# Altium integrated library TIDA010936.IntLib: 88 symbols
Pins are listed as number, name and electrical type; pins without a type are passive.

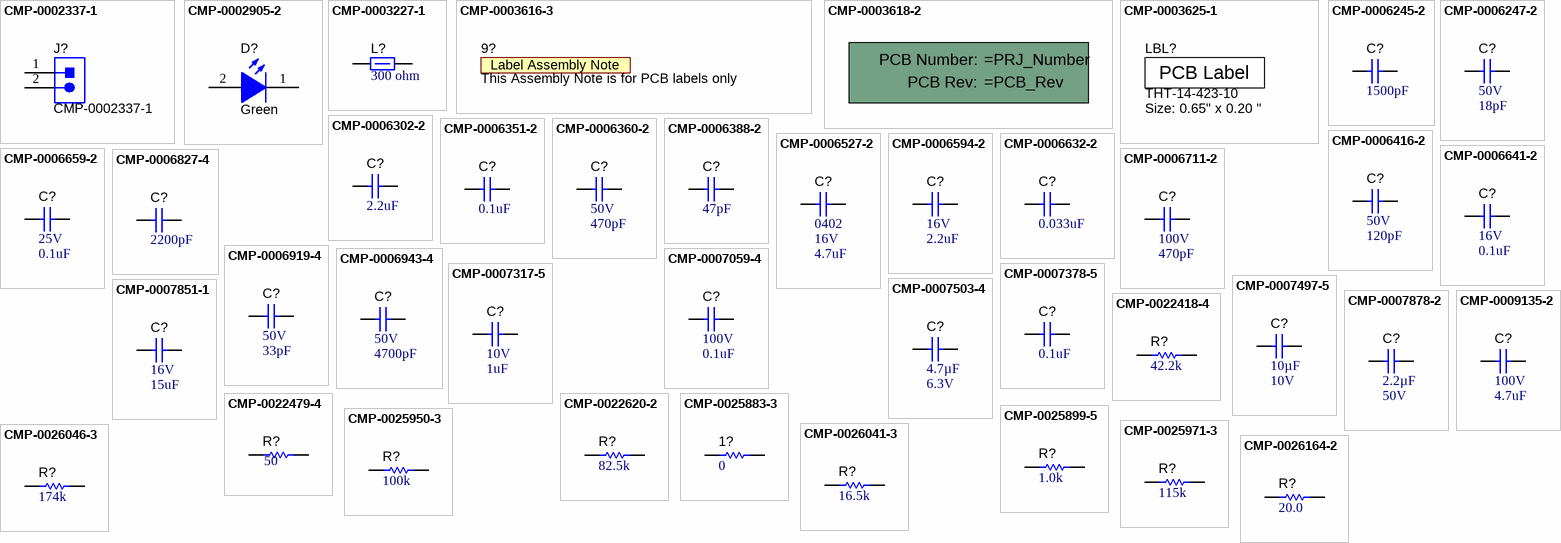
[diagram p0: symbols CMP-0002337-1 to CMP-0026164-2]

## CMP-0002337-1
designator J?
Header, 100mil, 2x1, Tin, TH; PartNumber: PEC02SAAN; Manufacturer: Sullins Connector Solutions; Pitch_mm: 2.54; Gender: Male; Shrouded: N; Row_Count: 1; Current_A: 3A; Voltage_V: 1.8kV; Cert_UL: Y; CNHeader: TRUE; Green_Lifecycle: Not Set; Green_REACh: Incomplete; CT: FALSE
footprint CONN_PEC02SAAN (SULLINS)
pins: 1, 2
1 alternate drawing of the same symbol

## CMP-0002905-2
designator D?  value Green  (hidden comment: CMP-0002905-2)
LED, Green, SMD; Manufacturer: Wurth Elektronik; PartNumber: 150060GS75000; Manufacturer: Wurth Electronics; Type: InGaN; Vf_V: 3.2V; Io_A: 20mA; Tjmax_C: 85°C; Value1: W; Angle: 140
footprint WL-SMCW_GREEN (WURTH)
pins: 1 K, 2 A

## CMP-0003227-1
designator L?  value 300 ohm  (hidden comment: CMP-0003227-1)
Ferrite Bead, 300 ohm @ 100 MHz, 0.2 A, 0402; PartNumber: 74279272; Manufacturer: Wurth Elektronik; Imax_A: 200mA; DCR_ohm: 0.8; Value1: 0.8 ohm; Value2: 0.2A; ZTyp@100MHz_Ohm: 300; Ztyp@1GHz_Ohm: 316.308; SizeAreaWB_mm2: 3; SizeZ_mm: 0.6; SizeX_mm: 1; SizeY_mm: 0.5
footprint 0402 (0402 from SM-752 data)
footprint 0402S (Based on C0402S footprint from PADS legacy)
footprint 0402L (0402 from SM-752 data)
footprint 0402M (0402 from SM-752 data)
pins: 1, 2

## CMP-0003616-3
designator 9?, comment This Assembly Note is for PCB labels only  (no BOM)
Key: AssemblyNoteLabel
footprint AssemblyNoteLabel (Assembly Note for PCB Labels)

## CMP-0003618-2
designator !PCB?, comment Printed Circuit Board  (value not drawn)  (mechanical)
Manufacturer: Any; CompType: PCB
1 alternate drawing of the same symbol

## CMP-0003625-1
designator LBL?, comment THT-14-423-10  Note: Size: 0.65" x 0.20 "
Thermal Transfer Printable Labels, 0.650" W x 0.200" H - 10,000 per roll; Manufacturer: Brady; CompType: Label
footprint Label_650x200 (Thermal Transfer Label)

## CMP-0006245-2
designator C?  ValueDisplayed: 1500pF  (hidden comment: CMP-0006245-2)
CAP, CERM, 1500 pF, 25 V, +/- 5%, C0G/NP0, 0402; PartNumber: C0402H152J3GAC7867; Manufacturer: Kemet; Polarized: N; CompType: Capacitor; Value: 1500pF; U/M: EA; Cap_F: 1.5nF; Value1: Unknown; VDC_V: 25V; TaMin_C: -55°C; TaMax_C: 200°C; Cap_Case: 0402; AEC Category: Q200; SizeArea_mm2: 0.5; SizeAreaWB_mm2: 3; SizeX_mm: 1; SizeZ_mm: 0.6
footprint 0402 (0402 from SM-752 data)
footprint 0402S (Based on C0402S footprint from PADS legacy)
footprint 0402L (0402 from SM-752 data)
footprint 0402M (0402 from SM-752 data)
pins: 1, 2

## CMP-0006247-2
designator C?, comment VDC_V: 50V  ValueDisplayed: 18pF  (hidden comment: C1005C0G1H180J050BA)
CAP, CERM, 18 pF, 50 V, +/- 5%, C0G/NP0, 0402; Manufacturer: TDK; TaMin_C: -55°C; Polarized: N; SizeAreaWB_mm2: 3; Value1: Unknown; U/M: EA; Value: 18pF; TaMax_C: 125°C; SizeZ_mm: 0.6; SizeX_mm: 1; SizeY_mm: 0.5; Cap_Case: 0402; CompType: Capacitor; AEC Category: Q200
footprint 0402 (0402 from SM-752 data)
footprint 0402S (Based on C0402S footprint from PADS legacy)
footprint 0402L (0402 from SM-752 data)
footprint 0402M (0402 from SM-752 data)
pins: 1, 2

## CMP-0006302-2
designator C?, comment ValueDisplayed: 2.2uF  (hidden comment: C1005X7S1A225K050BC)
CAP, CERM, 2.2 uF, 10 V, +/- 10%, X7S, 0402; Manufacturer: TDK; Polarized: N; CompType: Capacitor; Value: 2.2uF; U/M: EA; Cap_F: 2.2µF; ESR_ohm: 5.925m; Value1: 0.005925 ohm; VDC_V: 10V; IRMS_A: 2.0559A; TaMin_C: -55°C; TaMax_C: 125°C; Cap_Case: 0402_065; SizeArea_mm2: 0.5; SizeAreaWB_mm2: 3; SizeX_mm: 1; SizeZ_mm: 0.65; AEC Category: Q200
footprint 0402_065 (0402)
footprint 0402_065S (Based on C0402S footprint from PADS legacy)
footprint 0402_065L (0402)
footprint 0402_065M (0402)
pins: 1, 2

## CMP-0006351-2
designator C?  ValueDisplayed: 0.1uF  (hidden comment: CMP-0006351-2)
CAP, CERM, 0.1 uF, 16 V, +/- 10%, X7R, 0402; PartNumber: GCM155R71C104KA55D; Manufacturer: MuRata; Polarized: N; CompType: Capacitor; Value: 0.1uF; U/M: EA; Cap_F: 100nF; Value1: Unknown; VDC_V: 16V; TaMin_C: -55°C; TaMax_C: 125°C; Cap_Case: 0402; AEC Category: Q200; SizeAreaWB_mm2: 3; SizeZ_mm: 0.6; SizeX_mm: 1; SizeY_mm: 0.5
footprint 0402 (0402 from SM-752 data)
footprint 0402S (Based on C0402S footprint from PADS legacy)
footprint 0402L (0402 from SM-752 data)
footprint 0402M (0402 from SM-752 data)
pins: 1, 2

## CMP-0006360-2
designator C?, comment VDC_V: 50V  ValueDisplayed: 470pF  (hidden comment: GCM155R71H471KA37D)
CAP, CERM, 470 pF, 50 V, +/- 10%, X7R, AEC-Q200 Grade 1, 0402; Manufacturer: MuRata; TaMin_C: -55°C; Polarized: N; SizeAreaWB_mm2: 3; Value1: Unknown; U/M: EA; Value: 470pF; TaMax_C: 125°C; SizeZ_mm: 0.6; SizeX_mm: 1; SizeY_mm: 0.5; Cap_Case: 0402; CompType: Capacitor; AEC Qualified: Y; AEC Category: Q200
footprint 0402 (0402 from SM-752 data)
footprint 0402S (Based on C0402S footprint from PADS legacy)
footprint 0402L (0402 from SM-752 data)
footprint 0402M (0402 from SM-752 data)
pins: 1, 2

## CMP-0006388-2
designator C?  ValueDisplayed: 47pF  (hidden comment: CMP-0006388-2)
CAP, CERM, 47 pF, 25 V, +/- 5%, C0G/NP0, 0402; PartNumber: GRM1555C1E470JA01D; Manufacturer: MuRata; Polarized: N; CompType: Capacitor; Value: 47pF; U/M: EA; Value1: Unknown; VDC_V: 25V; TaMin_C: -55°C; TaMax_C: 125°C; Cap_Case: 0402; AEC Category: Q200; SizeAreaWB_mm2: 3; SizeZ_mm: 0.6; SizeX_mm: 1; SizeY_mm: 0.5
footprint 0402 (0402 from SM-752 data)
footprint 0402S (Based on C0402S footprint from PADS legacy)
footprint 0402L (0402 from SM-752 data)
footprint 0402M (0402 from SM-752 data)
pins: 1, 2

## CMP-0006416-2
designator C?, comment VDC_V: 50V  ValueDisplayed: 120pF  (hidden comment: GRM1555C1H121FA01D)
CAP, CERM, 120 pF, 50 V, +/- 1%, C0G/NP0, 0402; Manufacturer: MuRata; TaMin_C: -55°C; Polarized: N; SizeAreaWB_mm2: 3; Value1: Unknown; U/M: EA; Value: 120pF; TaMax_C: 125°C; SizeZ_mm: 0.6; SizeX_mm: 1; SizeY_mm: 0.5; Cap_Case: 0402; CompType: Capacitor; AEC Category: Q200
footprint 0402 (0402 from SM-752 data)
footprint 0402S (Based on C0402S footprint from PADS legacy)
footprint 0402L (0402 from SM-752 data)
footprint 0402M (0402 from SM-752 data)
pins: 1, 2

## CMP-0006527-2
designator C?, comment PackageReference: 0402  VDC_V: 16V  ValueDisplayed: 4.7uF  (hidden comment: GRM155D81C475ME15D)
CAP, CERM, 4.7 uF, 16 V, +/- 20%, X6T, 0402; Manufacturer: MuRata; TaMin_C: -55°C; Polarized: N; SizeAreaWB_mm2: 3; Value1: Unknown; U/M: EA; Value: 4.7uF; TaMax_C: 105°C; SizeZ_mm: 0.7; SizeX_mm: 1; SizeY_mm: 0.5; CompType: Capacitor; Cap_F: 4.7µF; AEC Category: Q200
footprint 0402_070 (SMD, 2-Leads, Body 1.2x0.7mm, Height 0.7mm)
pins: 1, 2

## CMP-0006594-2
designator C?, comment VDC_V: 16V  ValueDisplayed: 2.2uF  (hidden comment: GRM155R61C225KE11D)
CAP, CERM, 2.2 uF, 16 V, +/- 10%, X5R, 0402; Manufacturer: MuRata; TaMin_C: -55°C; Polarized: N; SizeAreaWB_mm2: 3; Value1: Unknown; U/M: EA; Value: 2.2uF; TaMax_C: 85°C; SizeZ_mm: 0.6; SizeX_mm: 1; SizeY_mm: 0.5; Cap_Case: 0402; CompType: Capacitor; Cap_F: 2.2µF; AEC Category: Q200
footprint 0402 (0402 from SM-752 data)
footprint 0402S (Based on C0402S footprint from PADS legacy)
footprint 0402L (0402 from SM-752 data)
footprint 0402M (0402 from SM-752 data)
pins: 1, 2

## CMP-0006632-2
designator C?  ValueDisplayed: 0.033uF  (hidden comment: CMP-0006632-2)
CAP, CERM, 0.033 uF, 10 V, +/- 10%, X7R, 0402; PartNumber: GRM155R71A333KA01D; Manufacturer: MuRata; Polarized: N; CompType: Capacitor; U/M: EA; Cap_F: 33nF; Value1: Unknown; VDC_V: 10V; TaMin_C: -55°C; TaMax_C: 125°C; Cap_Case: 0402; AEC Category: Q200; SizeArea_mm2: 0.5; SizeAreaWB_mm2: 3; SizeX_mm: 1; SizeZ_mm: 0.6
footprint 0402 (0402 from SM-752 data)
footprint 0402S (Based on C0402S footprint from PADS legacy)
footprint 0402L (0402 from SM-752 data)
footprint 0402M (0402 from SM-752 data)
pins: 1, 2

## CMP-0006641-2
designator C?, comment VDC_V: 16V  ValueDisplayed: 0.1uF  (hidden comment: GRM155R71C104KA88D)
CAP, CERM, 0.1 uF, 16 V, +/- 10%, X7R, 0402; Manufacturer: MuRata; Manufacturer Part Number: GRM155-R7-1C-104K-A88-D; TaMin_C: -55°C; Polarized: N; SizeAreaWB_mm2: 3; Value1: Unknown; U/M: EA; Value: 0.1uF; TaMax_C: 125°C; SizeZ_mm: 0.6; SizeX_mm: 1; SizeY_mm: 0.5; Cap_Case: 0402; CompType: Capacitor; Cap_F: 100nF; AEC Category: Q200
footprint 0402 (0402 from SM-752 data)
footprint 0402S (Based on C0402S footprint from PADS legacy)
footprint 0402L (0402 from SM-752 data)
footprint 0402M (0402 from SM-752 data)
pins: 1, 2

## CMP-0006659-2
designator C?, comment VDC_V: 25V  ValueDisplayed: 0.1uF  (hidden comment: GRM155R71E104KE14D)
CAP, CERM, 0.1 uF, 25 V, +/- 10%, X7R, 0402; Manufacturer: MuRata; TaMin_C: -55°C; Polarized: N; SizeAreaWB_mm2: 3; Value1: Unknown; U/M: EA; Value: 0.1uF; TaMax_C: 125°C; SizeZ_mm: 0.6; SizeX_mm: 1; SizeY_mm: 0.5; Cap_Case: 0402; CompType: Capacitor; Cap_F: 100nF; AEC Category: Q200
footprint 0402 (0402 from SM-752 data)
footprint 0402S (Based on C0402S footprint from PADS legacy)
footprint 0402L (0402 from SM-752 data)
footprint 0402M (0402 from SM-752 data)
pins: 1, 2

## CMP-0006711-2
designator C?, comment VDC_V: 100V  ValueDisplayed: 470pF  (hidden comment: GRM155R72A471KA01D)
CAP, CERM, 470 pF, 100 V, +/- 10%, X7R, 0402; Manufacturer: MuRata; TaMin_C: -55°C; Polarized: N; SizeAreaWB_mm2: 3; Value1: Unknown; U/M: EA; Value: 470pF; TaMax_C: 125°C; SizeZ_mm: 0.6; SizeX_mm: 1; SizeY_mm: 0.5; Cap_Case: 0402; CompType: Capacitor; AEC Category: Q200
footprint 0402 (0402 from SM-752 data)
footprint 0402S (Based on C0402S footprint from PADS legacy)
footprint 0402L (0402 from SM-752 data)
footprint 0402M (0402 from SM-752 data)
pins: 1, 2

## CMP-0006827-4
designator C?  ValueDisplayed: 2200pF  (hidden comment: CMP-0006827-4)
CAP, CERM, 2200 pF, 16 V, +/- 10%, X7R, 0603; PartNumber: 885012206036; Manufacturer: Wurth Elektronik; Polarized: N; CompType: Capacitor; Value: 2200pF; U/M: EA; Cap_F: 2.2nF; Value1: Unknown; VDC_V: 16V; TaMin_C: -55°C; TaMax_C: 125°C; Cap_Case: 0603; AEC Category: Q200; SizeArea_mm2: 1.28; SizeAreaWB_mm2: 4.68; SizeX_mm: 1.6; SizeY_mm: 0.8; SizeZ_mm: 1
footprint 0603 (0603 from SM-752 data)
footprint 0603_HV (Ernesto recommended land pattern.  26 mil between pads.)
footprint 0603L (0603 from SM-752 data)
footprint 0603S
footprint 0603M (0603 from SM-752 data)
pins: 1, 2

## CMP-0006919-4
designator C?, comment VDC_V: 50V  ValueDisplayed: 33pF  (hidden comment: C0603C330J5GACTU)
CAP, CERM, 33 pF, 50 V, +/- 5%, C0G/NP0, 0603; Manufacturer: Kemet; Manufacturer Part Number: C0603C180J5GAC-TU; TaMin_C: -55°C; Polarized: N; SizeAreaWB_mm2: 4.68; Value1: Unknown; U/M: EA; Value: 33pF; TaMax_C: 125°C; SizeZ_mm: 1; SizeX_mm: 1.6; SizeY_mm: 0.8; Cap_Case: 0603; SizeArea_mm2: 1.28; CompType: Capacitor; AEC Category: Q200
footprint 0603 (0603 from SM-752 data)
footprint 0603_HV (Ernesto recommended land pattern.  26 mil between pads.)
footprint 0603L (0603 from SM-752 data)
footprint 0603S
footprint 0603M (0603 from SM-752 data)
pins: 1, 2

## CMP-0006943-4
designator C?, comment VDC_V: 50V  ValueDisplayed: 4700pF  (hidden comment: C0603C472K5RACTU)
CAP, CERM, 4700 pF, 50 V, +/- 10%, X7R, 0603; Manufacturer: Kemet; TaMin_C: -55°C; Polarized: N; SizeAreaWB_mm2: 4.68; Value1: Unknown; U/M: EA; Value: 4700pF; TaMax_C: 125°C; SizeZ_mm: 1; SizeX_mm: 1.6; SizeY_mm: 0.8; Cap_Case: 0603; SizeArea_mm2: 1.28; CompType: Capacitor; Cap_F: 4.7nF; AEC Category: Q200
footprint 0603 (0603 from SM-752 data)
footprint 0603_HV (Ernesto recommended land pattern.  26 mil between pads.)
footprint 0603L (0603 from SM-752 data)
footprint 0603S
footprint 0603M (0603 from SM-752 data)
pins: 1, 2

## CMP-0007059-4
designator C?, comment VDC_V: 100V  ValueDisplayed: 0.1uF  (hidden comment: C1608X7S2A104K080AB)
CAP, CERM, 0.1 uF, 100 V, +/- 10%, X7S, 0603; Manufacturer: TDK; TaMin_C: -55°C; ESR_ohm: 49.59m; Polarized: N; SizeAreaWB_mm2: 4.68; Value1: 0.04959 ohm; U/M: EA; Value: 0.1uF; TaMax_C: 125°C; SizeZ_mm: 1; SizeX_mm: 1.6; SizeY_mm: 0.8; Cap_Case: 0603; SizeArea_mm2: 1.28; CompType: Capacitor; Cap_F: 100nF; IRMS_A: 751.618mA; AEC Category: Q200
footprint 0603 (0603 from SM-752 data)
footprint 0603_HV (Ernesto recommended land pattern.  26 mil between pads.)
footprint 0603L (0603 from SM-752 data)
footprint 0603S
footprint 0603M (0603 from SM-752 data)
pins: 1, 2

## CMP-0007317-5
designator C?, comment VDC_V: 10V  ValueDisplayed: 1uF  (hidden comment: GRM188R61A105KA61D)
CAP, CERM, 1 uF, 10 V, +/- 10%, X5R, 0603; Manufacturer: MuRata; TaMin_C: -55°C; Polarized: N; SizeAreaWB_mm2: 4.68; Value1: Unknown; U/M: EA; Value: 1uF; TaMax_C: 85°C; SizeZ_mm: 1; SizeX_mm: 1.6; SizeY_mm: 0.8; Cap_Case: 0603; SizeArea_mm2: 1.28; CompType: Capacitor; Cap_F: 1µF; AEC Category: Q200
footprint 0603 (0603 from SM-752 data)
footprint 0603_HV (Ernesto recommended land pattern.  26 mil between pads.)
footprint 0603L (0603 from SM-752 data)
footprint 0603S
footprint 0603M (0603 from SM-752 data)
pins: 1, 2

## CMP-0007378-5
designator C?  ValueDisplayed: 0.1uF  (hidden comment: CMP-0007378-5)
CAP, CERM, 0.1 uF, 16 V, +/- 10%, X7R, 0603; PartNumber: GRM188R71C104KA01D; Manufacturer: MuRata; Polarized: N; CompType: Capacitor; Value: 0.1uF; U/M: EA; Cap_F: 100nF; Value1: Unknown; VDC_V: 16V; TaMin_C: -55°C; TaMax_C: 125°C; Cap_Case: 0603; SizeAreaWB_mm2: 4.68; SizeZ_mm: 1; SizeX_mm: 1.6; SizeY_mm: 0.8; SizeArea_mm2: 1.28; AEC Category: Q200
footprint 0603 (0603 from SM-752 data)
footprint 0603_HV (Ernesto recommended land pattern.  26 mil between pads.)
footprint 0603L (0603 from SM-752 data)
footprint 0603S
footprint 0603M (0603 from SM-752 data)
pins: 1, 2

## CMP-0007497-5
designator C?, comment Cap_F: 10µF  VDC_V: 10V  (hidden comment: GRM188Z71A106MA73D)
CAP, CERM, 10 uF, 10 V, +/- 20%, X7R, 0603; Manufacturer: MuRata; TaMin_C: -55°C; Polarized: N; SizeAreaWB_mm2: 4.68; Value1: Unknown; U/M: EA; Value: 10uF; TaMax_C: 125°C; SizeZ_mm: 1; SizeX_mm: 1.6; SizeY_mm: 0.8; Cap_Case: 0603; SizeArea_mm2: 1.28; CompType: Capacitor; AEC Category: Q200
footprint 0603 (0603 from SM-752 data)
footprint 0603_HV (Ernesto recommended land pattern.  26 mil between pads.)
footprint 0603L (0603 from SM-752 data)
footprint 0603S
footprint 0603M (0603 from SM-752 data)
pins: 1, 2

## CMP-0007503-4
designator C?, comment Cap_F: 4.7µF  VDC_V: 6.3V  (hidden comment: JMK107BB7475MA-T)
CAP, CERM, 4.7 uF, 6.3 V, +/- 10%, X7R, 0603; Manufacturer: Taiyo Yuden; TaMin_C: -55°C; Polarized: N; SizeAreaWB_mm2: 4.68; Value1: Unknown; U/M: EA; Value: 4.7uF; TaMax_C: 125°C; SizeZ_mm: 1; SizeX_mm: 1.6; SizeY_mm: 0.8; Cap_Case: 0603; SizeArea_mm2: 1.28; CompType: Capacitor; AEC Category: Q200
footprint 0603 (0603 from SM-752 data)
footprint 0603_HV (Ernesto recommended land pattern.  26 mil between pads.)
footprint 0603L (0603 from SM-752 data)
footprint 0603S
footprint 0603M (0603 from SM-752 data)
pins: 1, 2

## CMP-0007851-1
designator C?, comment VDC_V: 16V  ValueDisplayed: 15uF  (hidden comment: C2012X6S1C156M125AC)
CAP, CERM, 15 uF, 16 V, +/- 20%, X6S, 0805; Manufacturer: TDK; TaMin_C: -55°C; ESR_ohm: 1.669m; Polarized: N; SizeAreaWB_mm2: 6.75; Value1: 0.001669 ohm; U/M: EA; Value: 15uF; TaMax_C: 105°C; SizeZ_mm: 1.45; SizeX_mm: 2; SizeY_mm: 1.25; Cap_Case: 0805; SizeArea_mm2: 2.5; CompType: Capacitor; Cap_F: 15µF; IRMS_A: 5.0498A; AEC Category: Q200
footprint 0805_HV (0805 with 30mil clearance between pads)
footprint 0805M (0805 from SM-752 data)
footprint 0805 (0805 from SM-752 data)
footprint 0805L (0805 from SM-752 data)
footprint 0805_HV1 (Custom footprint based on analyzing multiple manufacturer recommendations)
pins: 1, 2

## CMP-0007878-2
designator C?, comment Cap_F: 2.2µF  VDC_V: 50V  (hidden comment: C2012X7R1H225M125AC)
CAP, CERM, 2.2 uF, 50 V, +/- 20%, X7R, 0805; Manufacturer: TDK; TaMin_C: -55°C; Polarized: N; SizeAreaWB_mm2: 6.75; Value1: Unknown; U/M: EA; Value: 2.2uF; TaMax_C: 125°C; SizeZ_mm: 1.45; SizeX_mm: 2; SizeY_mm: 1.25; Cap_Case: 0805; SizeArea_mm2: 2.5; CompType: Capacitor; AEC Category: Q200
footprint 0805_HV (0805 with 30mil clearance between pads)
footprint 0805M (0805 from SM-752 data)
footprint 0805 (0805 from SM-752 data)
footprint 0805L (0805 from SM-752 data)
footprint 0805_HV1 (Custom footprint based on analyzing multiple manufacturer recommendations)
pins: 1, 2

## CMP-0009135-2
designator C?, comment VDC_V: 100V  ValueDisplayed: 4.7uF  (hidden comment: C3225X7S2A475K200AE)
CAP, CERM, 4.7 uF, 100 V, +/- 10%, X7S, 1210; Manufacturer: TDK; TaMin_C: -55°C; Polarized: N; SizeAreaWB_mm2: 14.7; Value1: Unknown; U/M: EA; Value: 4.7uF; TaMax_C: 125°C; SizeZ_mm: 1.35; SizeX_mm: 3.2; SizeY_mm: 2.5; Cap_Case: 1210; SizeArea_mm2: 8; CompType: Capacitor; Cap_F: 4.7µF; AEC Category: Q200
footprint 1210 (1210 from SM-752 data)
footprint 1210L (1210 from SM-752 data)
footprint 1210M (1210 from SM-752 data)
pins: 1, 2

## CMP-0022418-4
designator R?, comment ValueDisplayed: 42.2k  (hidden comment: CRCW060342K2FKEA)
RES, 42.2 k, 1%, 0.1 W, AEC-Q200 Grade 0, 0603; Manufacturer: Vishay-Dale; Manufacturer: Vishay/Dale; Power_W: 100mW; TempCo: 100 ppm/C; Value_Code: 42k2; Value: 42.2k; EIA_Code: E96; SizeX_mm: 1.6; SizeY_mm: 0.8; SizeZ_mm: 1; Value2: 0.1W; SizeArea_mm2: 1.28; CompType: Resistor; AEC Qualified: Y; VDC_V: 75V; AEC Category: Q200; AEC Grade: 0
footprint 0603 (0603 from SM-752 data)
footprint 0603_HV (Ernesto recommended land pattern.  26 mil between pads.)
footprint 0603L (0603 from SM-752 data)
footprint 0603S
footprint 0603M (0603 from SM-752 data)
pins: 1, 2

## CMP-0022479-4
designator R?, comment ValueDisplayed: 50  (hidden comment: CRCW060350R0FKEA)
RES, 50, 1%, 0.1 W, AEC-Q200 Grade 0, 0603; Manufacturer: Vishay-Dale; Manufacturer: Vishay / Dale; Power_W: 100mW; TempCo: 100 ppm/C; Value_Code: 50R0; Value: 50; SizeX_mm: 1.6; SizeY_mm: 0.8; SizeZ_mm: 1; Value2: 0.1W; SizeArea_mm2: 1.28; CompType: Resistor; AEC Qualified: Y; VDC_V: 75V; AEC Category: Q200; AEC Grade: 0
footprint 0603 (0603 from SM-752 data)
footprint 0603_HV (Ernesto recommended land pattern.  26 mil between pads.)
footprint 0603L (0603 from SM-752 data)
footprint 0603S
footprint 0603M (0603 from SM-752 data)
pins: 1, 2

## CMP-0022620-2
designator R?, comment ValueDisplayed: 82.5k  (hidden comment: CRCW060382K5FKEA)
RES, 82.5 k, 1%, 0.1 W, 0603; Manufacturer: Vishay-Dale; Manufacturer: Vishay/Dale; Power_W: 100mW; TempCo: 100 ppm/C; Value_Code: 82k5; U/M: EA; Value: 82.5k; EIA_Code: E96; SizeX_mm: 1.6; SizeY_mm: 0.8; SizeZ_mm: 1; Value2: 0.1W; SizeArea_mm2: 1.28; CompType: Resistor; VDC_V: 75V; AEC Category: Q200
footprint 0603 (0603 from SM-752 data)
footprint 0603_HV (Ernesto recommended land pattern.  26 mil between pads.)
footprint 0603L (0603 from SM-752 data)
footprint 0603S
footprint 0603M (0603 from SM-752 data)
pins: 1, 2

## CMP-0025883-3
designator 1?  ValueDisplayed: 0  (hidden comment: CMP-0025883-3)
RES, 0, 5%, 0.1 W, 0603; PartNumber: MCR03EZPJ000; Manufacturer: Rohm; CompType: Resistor; Value: 0; Value_Code: 0000; Power_W: 100mW; Value2: 0.1W; VDC_V: 50V; TempCo: 400 ppm/C; SizeArea_mm2: 1.28; SizeX_mm: 1.6; SizeY_mm: 0.8; SizeZ_mm: 1; EIA_Code: E24; U/M: EA; AEC Category: Q200; AEC Qualified: N
footprint 0603 (0603 from SM-752 data)
footprint 0603_HV (Ernesto recommended land pattern.  26 mil between pads.)
footprint 0603L (0603 from SM-752 data)
footprint 0603S
footprint 0603M (0603 from SM-752 data)
pins: 1, 2

## CMP-0025899-5
designator R?, comment ValueDisplayed: 1.0k  (hidden comment: RC0603JR-071KL)
RES, 1.0 k, 5%, 0.1 W, 0603; Manufacturer: Yageo; Power_W: 100mW; TempCo: 100 ppm/C; Value_Code: 1k00; Value: 1.0k; EIA_Code: E24; Res_ohm: 1k; SizeX_mm: 1.6; SizeY_mm: 0.8; SizeZ_mm: 1; Value2: 0.1W; SizeArea_mm2: 1.28; CompType: Resistor; AEC Qualified: N; VDC_V: 75V; AEC Category: Q200; SizeAreaWB_mm2: 4.68
footprint 0603 (0603 from SM-752 data)
footprint 0603_HV (Ernesto recommended land pattern.  26 mil between pads.)
footprint 0603L (0603 from SM-752 data)
footprint 0603S
footprint 0603M (0603 from SM-752 data)
pins: 1, 2

## CMP-0025950-3
designator R?  ValueDisplayed: 100k  (hidden comment: CMP-0025950-3)
RES, 100 k, 1%, 0.063 W, AEC-Q200 Grade 0, 0402; PartNumber: CRCW0402100KFKED; Manufacturer: Vishay-Dale; Manufacturer: Vishay / Dale; CompType: Resistor; Value: 100k; Power_W: 63mW; Value2: 0.063W; VDC_V: 50V; TempCo: 100 ppm/C; EIA_Code: E96; AEC Category: Q200; AEC Qualified: Y; AEC Grade: 0; SizeArea_mm2: 0.5; SizeX_mm: 1; SizeZ_mm: 0.6
footprint 0402 (0402 from SM-752 data)
footprint 0402S (Based on C0402S footprint from PADS legacy)
footprint 0402L (0402 from SM-752 data)
footprint 0402M (0402 from SM-752 data)
pins: 1, 2

## CMP-0025971-3
designator R?, comment ValueDisplayed: 115k  (hidden comment: CRCW0402115KFKED)
RES, 115 k, 1%, 0.063 W, AEC-Q200 Grade 0, 0402; Manufacturer: Vishay-Dale; Manufacturer: Vishay / Dale; Power_W: 63mW; TempCo: 100 ppm/C; Value: 115k; EIA_Code: E96; SizeX_mm: 1; SizeY_mm: 0.5; SizeZ_mm: 0.6; Value2: 0.063W; CompType: Resistor; AEC Qualified: Y; VDC_V: 50V; AEC Category: Q200; AEC Grade: 0
footprint 0402 (0402 from SM-752 data)
footprint 0402S (Based on C0402S footprint from PADS legacy)
footprint 0402L (0402 from SM-752 data)
footprint 0402M (0402 from SM-752 data)
pins: 1, 2

## CMP-0026041-3
designator R?, comment ValueDisplayed: 16.5k  (hidden comment: CRCW040216K5FKED)
RES, 16.5 k, 1%, 0.063 W, AEC-Q200 Grade 0, 0402; Manufacturer: Vishay-Dale; Manufacturer: Vishay / Dale; Power_W: 63mW; TempCo: 100 ppm/C; Value_Code: 16k5; Value: 16.5k; EIA_Code: E96; SizeX_mm: 1; SizeY_mm: 0.5; SizeZ_mm: 0.6; Value2: 0.063W; CompType: Resistor; AEC Qualified: Y; VDC_V: 50V; AEC Category: Q200; AEC Grade: 0
footprint 0402 (0402 from SM-752 data)
footprint 0402S (Based on C0402S footprint from PADS legacy)
footprint 0402L (0402 from SM-752 data)
footprint 0402M (0402 from SM-752 data)
pins: 1, 2

## CMP-0026046-3
designator R?, comment ValueDisplayed: 174k  (hidden comment: CRCW0402174KFKED)
RES, 174 k, 1%, 0.063 W, AEC-Q200 Grade 0, 0402; Manufacturer: Vishay-Dale; Manufacturer: Vishay / Dale; Power_W: 63mW; TempCo: 100 ppm/C; Value: 174k; EIA_Code: E96; SizeX_mm: 1; SizeY_mm: 0.5; SizeZ_mm: 0.6; Value2: 0.063W; CompType: Resistor; AEC Qualified: Y; VDC_V: 50V; AEC Category: Q200; AEC Grade: 0
footprint 0402 (0402 from SM-752 data)
footprint 0402S (Based on C0402S footprint from PADS legacy)
footprint 0402L (0402 from SM-752 data)
footprint 0402M (0402 from SM-752 data)
pins: 1, 2

## CMP-0026164-2
designator R?  ValueDisplayed: 20.0  (hidden comment: CMP-0026164-2)
RES, 20.0, 1%, 0.063 W, AEC-Q200 Grade 0, 0402; PartNumber: CRCW040220R0FKED; Manufacturer: Vishay-Dale; CompType: Resistor; Value: 20.0; Res_ohm: 20; Value_Code: 20R0; Power_W: 63mW; Value2: 0.063W; VDC_V: 50V; TempCo: 100 ppm/C; EIA_Code: E96; AEC Category: Q200; AEC Qualified: Y; AEC Grade: 0; SizeX_mm: 1; SizeY_mm: 0.5; SizeZ_mm: 0.6
footprint 0402 (0402 from SM-752 data)
footprint 0402S (Based on C0402S footprint from PADS legacy)
footprint 0402L (0402 from SM-752 data)
footprint 0402M (0402 from SM-752 data)
pins: 1, 2

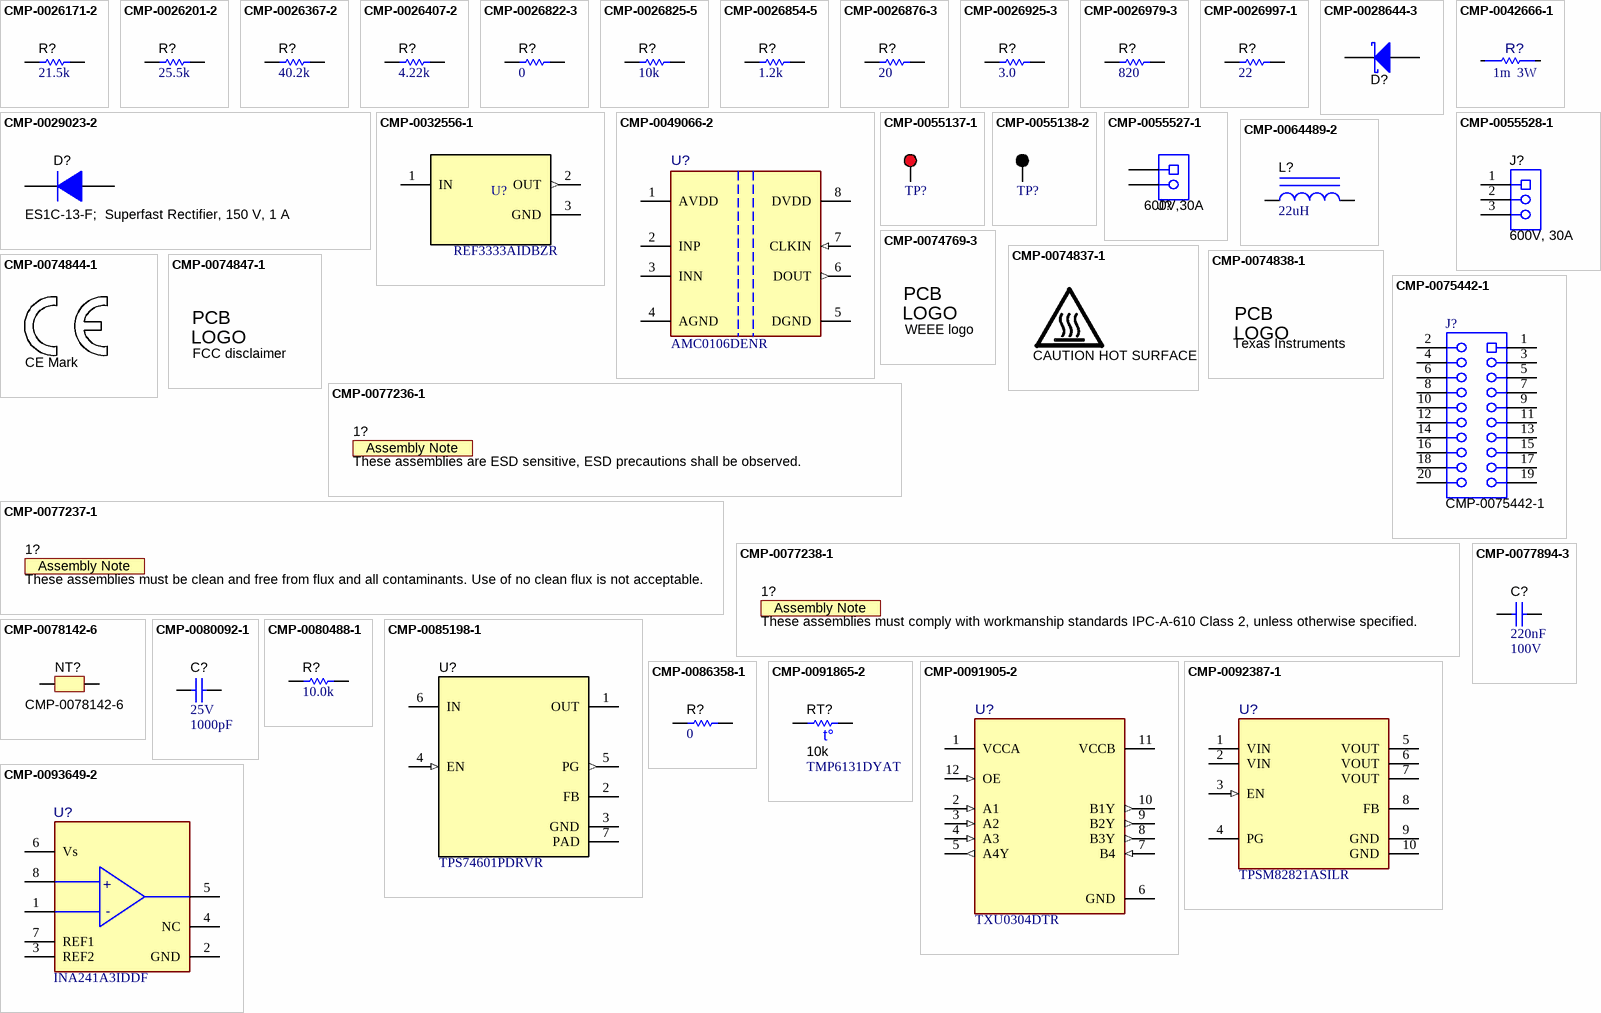
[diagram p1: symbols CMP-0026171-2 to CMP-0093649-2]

## CMP-0026171-2
designator R?, comment ValueDisplayed: 21.5k  (hidden comment: CRCW040221K5FKED)
RES, 21.5 k, 1%, 0.063 W, AEC-Q200 Grade 0, 0402; Manufacturer: Vishay-Dale; Power_W: 63mW; TempCo: 100 ppm/C; Value_Code: 21k5; Value: 21.5k; EIA_Code: E96; SizeX_mm: 1; SizeY_mm: 0.5; SizeZ_mm: 0.6; Value2: 0.063W; CompType: Resistor; AEC Qualified: Y; VDC_V: 50V; AEC Category: Q200; AEC Grade: 0
footprint 0402 (0402 from SM-752 data)
footprint 0402S (Based on C0402S footprint from PADS legacy)
footprint 0402L (0402 from SM-752 data)
footprint 0402M (0402 from SM-752 data)
pins: 1, 2

## CMP-0026201-2
designator R?, comment ValueDisplayed: 25.5k  (hidden comment: CRCW040225K5FKED)
RES, 25.5 k, 1%, 0.063 W, AEC-Q200 Grade 0, 0402; Manufacturer: Vishay-Dale; Power_W: 63mW; TempCo: 100 ppm/C; Value_Code: 25k5; Value: 25.5k; EIA_Code: E96; SizeX_mm: 1; SizeY_mm: 0.5; SizeZ_mm: 0.6; Value2: 0.063W; CompType: Resistor; AEC Qualified: Y; VDC_V: 50V; AEC Category: Q200; AEC Grade: 0
footprint 0402 (0402 from SM-752 data)
footprint 0402S (Based on C0402S footprint from PADS legacy)
footprint 0402L (0402 from SM-752 data)
footprint 0402M (0402 from SM-752 data)
pins: 1, 2

## CMP-0026367-2
designator R?, comment ValueDisplayed: 40.2k  (hidden comment: CRCW040240K2FKED)
RES, 40.2 k, 1%, 0.063 W, AEC-Q200 Grade 0, 0402; Manufacturer: Vishay-Dale; Power_W: 63mW; TempCo: 100 ppm/C; Value_Code: 40k2; Value: 40.2k; EIA_Code: E96; SizeX_mm: 1; SizeY_mm: 0.5; SizeZ_mm: 0.6; Value2: 0.063W; CompType: Resistor; AEC Qualified: Y; VDC_V: 50V; AEC Category: Q200; AEC Grade: 0
footprint 0402 (0402 from SM-752 data)
footprint 0402S (Based on C0402S footprint from PADS legacy)
footprint 0402L (0402 from SM-752 data)
footprint 0402M (0402 from SM-752 data)
pins: 1, 2

## CMP-0026407-2
designator R?  ValueDisplayed: 4.22k  (hidden comment: CMP-0026407-2)
RES, 4.22 k, 1%, 0.063 W, AEC-Q200 Grade 0, 0402; PartNumber: CRCW04024K22FKED; Manufacturer: Vishay-Dale; CompType: Resistor; Value: 4.22k; Value_Code: 4k22; Power_W: 63mW; Value2: 0.063W; VDC_V: 50V; TempCo: 100 ppm/C; EIA_Code: E96; AEC Category: Q200; AEC Qualified: Y; AEC Grade: 0; SizeArea_mm2: 0.5; SizeX_mm: 1; SizeZ_mm: 0.6
footprint 0402 (0402 from SM-752 data)
footprint 0402S (Based on C0402S footprint from PADS legacy)
footprint 0402L (0402 from SM-752 data)
footprint 0402M (0402 from SM-752 data)
pins: 1, 2

## CMP-0026822-3
designator R?  ValueDisplayed: 0  (hidden comment: CMP-0026822-3)
RES, 0, 5%, 0.063 W, AEC-Q200 Grade 0, 0402; PartNumber: CRCW04020000Z0ED; Manufacturer: Vishay-Dale; Manufacturer: Vishay / Dale; CompType: Resistor; Value: 0; Value_Code: 0000; Power_W: 63mW; Value2: 0.063W; VDC_V: 50V; TempCo: 200 ppm/C; SizeArea_mm2: 0.5; SizeX_mm: 1; SizeZ_mm: 0.6; EIA_Code: E24; AEC Category: Q200; AEC Qualified: Y
footprint 0402 (0402 from SM-752 data)
footprint 0402S (Based on C0402S footprint from PADS legacy)
footprint 0402L (0402 from SM-752 data)
footprint 0402M (0402 from SM-752 data)
pins: 1, 2

## CMP-0026825-5
designator R?  ValueDisplayed: 10k  (hidden comment: CMP-0026825-5)
RES, 10 k, 5%, 0.063 W, AEC-Q200 Grade 0, 0402; PartNumber: CRCW040210K0JNED; Manufacturer: Vishay-Dale; Manufacturer: Vishay / Dale; CompType: Resistor; Value: 10k; Value_Code: 10k0; Power_W: 63mW; Value2: 0.063W; VDC_V: 50V; TempCo: 200 ppm/C; SizeArea_mm2: 0.5; SizeX_mm: 1; SizeZ_mm: 0.6; EIA_Code: E24; AEC Category: Q200; AEC Qualified: Y; AEC Grade: 0
footprint 0402 (0402 from SM-752 data)
footprint 0402S (Based on C0402S footprint from PADS legacy)
footprint 0402L (0402 from SM-752 data)
footprint 0402M (0402 from SM-752 data)
pins: 1, 2

## CMP-0026854-5
designator R?  ValueDisplayed: 1.2k  (hidden comment: CMP-0026854-5)
RES, 1.2 k, 5%, 0.063 W, AEC-Q200 Grade 0, 0402; PartNumber: CRCW04021K20JNED; Manufacturer: Vishay-Dale; Manufacturer: Vishay / Dale; CompType: Resistor; Value: 1.2k; Value_Code: 1k20; Power_W: 63mW; Value2: 0.063W; VDC_V: 50V; TempCo: 200 ppm/C; EIA_Code: E24; AEC Category: Q200; AEC Qualified: Y; AEC Grade: 0; SizeArea_mm2: 0.5; SizeX_mm: 1; SizeZ_mm: 0.6
footprint 0402 (0402 from SM-752 data)
footprint 0402S (Based on C0402S footprint from PADS legacy)
footprint 0402L (0402 from SM-752 data)
footprint 0402M (0402 from SM-752 data)
pins: 1, 2

## CMP-0026876-3
designator R?  ValueDisplayed: 20  (hidden comment: CMP-0026876-3)
RES, 20, 5%, 0.063 W, AEC-Q200 Grade 0, 0402; PartNumber: CRCW040220R0JNED; Manufacturer: Vishay-Dale; Manufacturer: Vishay / Dale; CompType: Resistor; Value: 20; Value_Code: 20R0; Power_W: 63mW; Value2: 0.063W; VDC_V: 50V; TempCo: 200 ppm/C; EIA_Code: E24; AEC Category: Q200; AEC Qualified: Y; AEC Grade: 0; SizeArea_mm2: 0.5; SizeX_mm: 1; SizeZ_mm: 0.6
footprint 0402 (0402 from SM-752 data)
footprint 0402S (Based on C0402S footprint from PADS legacy)
footprint 0402L (0402 from SM-752 data)
footprint 0402M (0402 from SM-752 data)
pins: 1, 2

## CMP-0026925-3
designator R?, comment ValueDisplayed: 3.0  (hidden comment: CRCW04023R00JNED)
RES, 3.0, 5%, 0.063 W, AEC-Q200 Grade 0, 0402; Manufacturer: Vishay-Dale; Manufacturer: Vishay / Dale; Power_W: 63mW; TempCo: 200 ppm/C; Value_Code: 3R00; Value: 3.0; EIA_Code: E24; Res_ohm: 3; SizeX_mm: 1; SizeY_mm: 0.5; SizeZ_mm: 0.6; Value2: 0.063W; CompType: Resistor; AEC Qualified: Y; VDC_V: 50V; AEC Category: Q200; AEC Grade: 0
footprint 0402 (0402 from SM-752 data)
footprint 0402S (Based on C0402S footprint from PADS legacy)
footprint 0402L (0402 from SM-752 data)
footprint 0402M (0402 from SM-752 data)
pins: 1, 2

## CMP-0026979-3
designator R?  ValueDisplayed: 820  (hidden comment: CMP-0026979-3)
RES, 820, 5%, 0.063 W, AEC-Q200 Grade 0, 0402; PartNumber: CRCW0402820RJNED; Manufacturer: Vishay-Dale; Manufacturer: Vishay / Dale; CompType: Resistor; Value: 820; Value_Code: 820R; Power_W: 63mW; Value2: 0.063W; VDC_V: 50V; TempCo: 200 ppm/C; EIA_Code: E24; AEC Category: Q200; AEC Qualified: Y; AEC Grade: 0; SizeX_mm: 1; SizeY_mm: 0.5; SizeZ_mm: 0.6
footprint 0402 (0402 from SM-752 data)
footprint 0402S (Based on C0402S footprint from PADS legacy)
footprint 0402L (0402 from SM-752 data)
footprint 0402M (0402 from SM-752 data)
pins: 1, 2

## CMP-0026997-1
designator R?, comment ValueDisplayed: 22  (hidden comment: ERJ-2GEJ220X)
RES, 22, 5%, 0.1 W, AEC-Q200 Grade 0, 0402; Manufacturer: Panasonic; Power_W: 100mW; TempCo: 200 ppm/C; Value_Code: 22R0; U/M: EA; Value: 22; EIA_Code: E24; SizeX_mm: 1; SizeY_mm: 0.5; SizeZ_mm: 0.6; Value2: 0.1W; CompType: Resistor; AEC Qualified: Y; AEC Grade: 0; AEC Category: Q200
footprint 0402 (0402 from SM-752 data)
footprint 0402S (Based on C0402S footprint from PADS legacy)
footprint 0402L (0402 from SM-752 data)
footprint 0402M (0402 from SM-752 data)
pins: 1, 2

## CMP-0028644-3
designator D?  (value not drawn)
Diode, Schottky, 70 V, 0.07 A, SOD-523; PartNumber: 1PS79SB70,115; Manufacturer: Nexperia; Vf_V: 410mV; Value: 70V; Value1: 0.07A; Value2: 0.41V; Io_A: 70mA; TJmax_C: 150°C; SizeAreaWB_mm2: 5.13; SizeArea_mm2: 1.53; SizeX_mm: 1.7; SizeY_mm: 0.9; SizeZ_mm: 0.65; AEC Category: Q101; Green_Lifecycle: Not Set; Green_REACh: Incomplete
footprint SOD-523 (NXP Semiconductor recommended land pattern, nominal STEP model)
pins: 1 K, 2 A

## CMP-0029023-2
designator D?, comment ES1C-13-F;  Superfast Rectifier, 150 V, 1 A
Diode, Superfast Rectifier, 150 V, 1 A, SMA; Manufacturer: Diodes Inc.; Manufacturer: Diodes; TJmax_C: 150°C; Vr_V: 150V; Value2: 0.92V; SizeX_mm: 5.59; Green_REACh: Incomplete; SizeAreaWB_mm2: 37.3428; Value: 150V; Vf_V: 920mV; Green_Lifecycle: Not Set; Value1: 1A; SizeZ_mm: 2.87; SizeArea_mm2: 16.3228; SizeY_mm: 2.92; AEC Category: Q101; RJC_CperW: 25
footprint SMA (Molded Diode, 2-Leads, Body 4.3x2.6mm, IPC Medium Density, based on OnSemi component dimensions and land pattern)
pins: 1 K, 2 A

## CMP-0032556-1
designator U?, comment REF3333AIDBZR
30 ppm / degC Drift, 3.9 uA Voltage Reference, -40 to 125 degC, 3-pin SOT-23 (DBZ), Green (RoHS & no Sb/Br); Manufacturer: Texas Instruments; Initial Accuracy @ 25/deg C(%): 0.15; Iout/Iz(Max)(mA): 5; Rating: Catalog; SubFamily: Series Voltage Reference; Temp Coeff(Max)(ppm/ degree C): 30; Temp Coeff(Typ)(ppm/ degree C): 8; VI(Max)(V): 5.5; VI(Min)(V): 3.5; VO(V): 3.3
footprint DBZ0003A_N (SOT23, 3-Leads, Body 2.9x1.3mm, Pitch 0.95mm, Lead Span 2.4mm, IPC Medium Density)
footprint DBZ0003A_M (SOT23, 3-Leads, Body 2.9x1.3mm, Pitch 0.95mm, Lead Span 2.4mm, IPC Low Density)
footprint DBZ0003A_L (SOT23, 3-Leads, Body 2.9x1.3mm, Pitch 0.95mm, Lead Span 2.4mm, IPC High Density)
pins: 1 IN (power), 2 OUT (out), 3 GND (power)

## CMP-0042666-1
designator R?, comment value 1m  Power_W: 3W  (hidden comment: ULRG32512R001FLFSLT)
Res Metal Strip 2512 0.001 Ohm 1% 3W ±50ppm/C Pad SMD Automotive T/R; Manufacturer: TT Electronics; Manufacturer: TT IRC; Manufacturer Part Number: ULRG3-2512-R001-F-LF-SLT; AEC Grade: Grade 0; AEC Qualified: Yes; SizeZ_mm: 0.8mm; TempCo: 50ppm/°C; TaMax_C: +170°C; TaMin_C: -55°C
footprint FP-ULRG32512R001FLFSLT_2512-MFG
pins: 1, 2

## CMP-0049066-2
designator U?, comment AMC0106DENR
±50 mV Input Functionally Isolated Delta-Sigma Modulator for Current Sensing, VSON8; Manufacturer: Texas Instruments; SizeZ_mm: 1mm; Interface: SPI; Standoff Height: 0mm; AEC Category: Q200; CompType: IC
footprint DEN0008A-MFG
footprint DEN0008A-MFG-NO_VIA
pins: 1 AVDD (power), 2 INP, 3 INN, 4 AGND (power), 5 DGND (power), 6 DOUT (out), 7 CLKIN (in), 8 DVDD (power)

## CMP-0055137-1
designator TP?, comment 5000  (value not drawn)
Test Point, Miniature, Red, TH; Manufacturer: Keystone; Manufacturer: Keystone Electronics; CNHeader: FALSE; Green_Lifecycle: Active; Green_REACh: Passed; ContactFinish: Silver; CT: TRUE
footprint Keystone5000 (For Keystone 500x miniature loop terminals)
pins: 1

## CMP-0055138-2
designator TP?  (value not drawn)
Test Point, Miniature, Black, TH; PartNumber: 5001; Manufacturer: Keystone Electronics; ContactFinish: Silver; CNHeader: FALSE; Green_Lifecycle: Active; Green_REACh: Passed; CT: TRUE
footprint Keystone5001 (For Keystone 500x miniature loop terminals)
pins: 1

## CMP-0055527-1
designator J?, comment 600V,30A
Terminal Block, 9.52mm, 2x1, R/A, TH; PartNumber: 1902547; Manufacturer: Phoenix Contact; Pitch_mm: 9.52; Gender: Female; Row_Count: 1; Current_A: 32A; Voltage_V: 1kV; Cert_UL: Y; CNHeader: FALSE; CT: TRUE
footprint Phoenix_1902547 (TH, 2-Leads, Body 19.04x16mm, Pitch 9.52mm)
pins: 1, 2

## CMP-0055528-1
designator J?, comment 600V, 30A
Terminal Block, 9.52mm, 3x1, R/A, TH; Manufacturer: Phoenix Contact; PartNumber: 1904150; Cert_VDE: Y; CNHeader: FALSE; Current_A: 32A; Gender: Female; Voltage_V: 1kV; Row_Count: 1; Pitch_mm: 9.52; CT: TRUE
footprint Phoenix_1904150 (TH, 3-Leads, Body 28.56x16mm, Pitch 9.52mm)
pins: 1, 2, 3

## CMP-0064489-2
designator L?, comment ValueDisplayed: 22uH  (hidden comment: 74437324220)
Inductor, Shielded Drum Core, Powdered Iron, 22 uH, 1 A, 0.47 ohm, SMD; Manufacturer: Wurth Elektronik; Isat: 2A @ 20% inductance drop; Irms: 1A @ 40C rise; Green_Lifecycle: Active; SizeAreaWB_mm2: 27.577; DCR_ohm: 0.47; Green_REACh: Passed; Value: 22uH; Imax_A: 1A; SizeZ_mm: 2; SizeX_mm: 4.45; SizeY_mm: 4.06; SizeArea_mm2: 18.067; Ind_H: 22µH; AEC Category: Q200
footprint WE-LHMI_4020 (WERTH)
pins: 1, 2

## CMP-0074769-3
designator 5?, comment WEEE logo  (no BOM)
Manufacturer: Texas Instruments; CompType: IC; AEC Category: Q200
footprint WEEE_Minimum (WEEElie bin)

## CMP-0074837-1
designator 6?, comment CAUTION HOT SURFACE  (no BOM)
IEC 61010-1 Hot Surface Warning; Library Reference: IEC_HotSurface; SymbolCreator: a0412235
footprint IEC_HotSurface_Large
footprint IEC_HotSurface_Small
footprint IEC_HotSurface_Medium

## CMP-0074838-1
designator 3?, comment Texas Instruments  (no BOM)
Texas Instrument Corporate Signature; SymbolCreator: a0412235; Lib Reference: TI_Logo; Library Reference: Logo
footprint TI_Horizontal_Overlay_Medium
footprint TI_Horizontal_Overlay_Small
footprint TI_Stacked_SolderMask_Small
footprint TI_Stacked_SolderMask_Small_Vertical
footprint TI_Symbol_Overlay_Medium
footprint TI_Symbol_Overlay_Small
footprint TI_Symbol_SolderMask_Medium
footprint TI_Symbol_SolderMask_Small
footprint TI_Horizontal_SolderMask_Medium
footprint TI_Horizontal_SolderMask_Small
footprint TI_Stacked_Overlay_Medium
footprint TI_Stacked_Overlay_Medium_Vertical
footprint TI_Stacked_Overlay_Small
footprint TI_Stacked_Overlay_Small_Vertical
footprint TI_Stacked_SolderMask_Medium
footprint TI_Stacked_SolderMask_Medium_Vertical

## CMP-0074844-1
designator 2?, comment CE Mark  (no BOM)
SymbolCreator: a0412235
footprint CE_Mark_5mm (Minimum text height for CE Mark)
footprint CE_Mark_10mm (Double the minimum text height for CE Mark)

## CMP-0074847-1
designator 4?, comment FCC disclaimer  (no BOM)
FCC_disclaimer; Library Reference: Logo
footprint FCC_disclaimer
footprint FCC_disclaimer_stacked

## CMP-0075442-1
designator J?
Connector, Receptacle, 100mil, 10x2, Gold plated, TH; PartNumber: SSW-110-23-F-D; Manufacturer: Samtec; CompType: Socket Strip; Green_Lifecycle: Active; Green_REACh: Passed; CT: True; CNHeader: False
footprint CONN_SSW-110-23-F-D (SAMTEC)
pins: 1, 2, 3, 4, 5, 6, 7, 8, 9, 10, 11, 12, 13, 14, 15, 16, 17, 18, 19, 20

## CMP-0077236-1
designator 1?, comment These assemblies are ESD sensitive, ESD precautions shall be observed.  (no BOM)
CompType: AssemblyNote
footprint AssemblyNote (Assembly Note)

## CMP-0077237-1
designator 1?, comment These assemblies must be clean and free from flux and all contaminants. Use of no clean flux is not acceptable.  (no BOM)
CompType: AssemblyNote
footprint AssemblyNote (Assembly Note)

## CMP-0077238-1
designator 1?, comment These assemblies must comply with workmanship standards IPC-A-610 Class 2, unless otherwise specified.  (no BOM)
CompType: AssemblyNote
footprint AssemblyNote (Assembly Note)

## CMP-0077894-3
designator C?, comment Cap_F: 220nF  VDC_V: 100V  (hidden comment: HMK107C7224KAHTE)
CAP, CERM, 0.22 µF, 100 V,+/- 10%, X7S, AEC-Q200 Grade 1, 0603; Manufacturer: Taiyo Yuden; TaMin_C: -55°C; Polarized: N; SizeAreaWB_mm2: 4.68; U/M: EA; Value: 0.22uF; TaMax_C: 125°C; SizeZ_mm: 1.0; SizeX_mm: 1.6; SizeY_mm: 0.8; Cap_Case: 0603; SizeArea_mm2: 1.28; CompType: Capacitor; AEC Qualified: Y; AEC Category: Q200; ValueDisplayed: 0.22µF; AEC Grade: 1
footprint 0603 (0603 from SM-752 data)
footprint 0603_HV (Ernesto recommended land pattern.  26 mil between pads.)
footprint 0603L (0603 from SM-752 data)
footprint 0603S
footprint 0603M (0603 from SM-752 data)
pins: 1, 2

## CMP-0078142-6
designator NT?  (net tie, no BOM)
Single point connection between nets.; Library Reference: Net-Tie
footprint Net-Tie_0805_HV_NoOverlay (0805_HV pads tied by 10mil copper trace which can be cut.  An 0805 part can be placed on pads.)
footprint Net-Tie_10milWide_30milLong (10mil net tie, no solder mask opening, no solder paste)
footprint NetTie_0402 (Net Tie 0402 size)
footprint Net-Tie_50milWide_30milLong (50mil net tie, no solder mask opening, no solder paste)
footprint Net-Tie_20milWide_60milLong (20mil net tie, no solder mask opening, no solder paste)
footprint Net-Tie_6mil (10mil net tie, no solder mask opening, no solder paste)
footprint NetTie_1206_NoOverlay (1206 pads tied by 10mil copper trace which can be cut.  Part can be placed on pads.)
footprint Net-Tie_0805_HV (0805_HV pads tied by 10mil copper trace which can be cut.  An 0805 part can be placed on pads.)
footprint NetTie_1206 (1206 pads tied by 10mil copper trace which can be cut.  Part can be placed on pads.)
footprint Net-Tie_5milWide_60milLong (5mil net tie, no solder mask opening, no solder paste)
footprint NetTie_0603 (Net Tie 0603 size)
footprint Net-Tie_4x6mil
footprint Net-Tie_6x8mil
footprint Net-Tie_4milsWide_10milsLong (Net-Tie 4 mils wide by 10 mils long)
footprint Net-Tie6milsWide_20milsLong (6 mils wide by 20 mils long)
footprint Net-Tie7milsWide_20milsLong (7 mils wide by 20 mils long)
footprint Net-Tie_10mil (10mil net tie, no solder mask opening, no solder paste)
pins: 1, 2

## CMP-0080092-1
designator C?, comment VDC_V: 25V  ValueDisplayed: 1000pF  (hidden comment: C0603C102F3GACTU)
CAP, CERM, 1000 pF, 25 V,+/- 1%, C0G/NP0, 0603; Manufacturer: Kemet; Cap_F: 1nF; SizeAreaWB_mm2: 4.68; SizeArea_mm2: 1.28; AEC Qualified: N; AEC Category: Q200; Value: 1000pF; TaMax_C: 125°C; SizeZ_mm: 1; Green_REACh: Passed; TaMin_C: -55°C; SizeY_mm: 0.8; Green_Lifecycle: Active; U/M: EA; CompType: Capacitor; SizeX_mm: 1.6; Cap_Case: 0603
footprint 0603 (0603 from SM-752 data)
footprint 0603M (0603 from SM-752 data)
footprint 0603L (0603 from SM-752 data)
footprint 0603_HV (Ernesto recommended land pattern.  26 mil between pads.)
footprint 0603S
pins: 1, 2

## CMP-0080488-1
designator R?, comment ValueDisplayed: 10.0k  (hidden comment: M55342K12B10E0T)
RES, 10.0 k, 1%, 0.1 W, 0603; Manufacturer: TT Electronics/IRC; Power_W: 100mW; TempCo: 100 ppm/C; SizeAreaWB_mm2: 4.68; Value_Code: 10k0; Value: 10.0k; EIA_Code: E96; Res_ohm: 10k; SizeX_mm: 1.6; SizeY_mm: 0.8; SizeZ_mm: 1; Value2: 0.1W; SizeArea_mm2: 1.28; CompType: Resistor; AEC Qualified: N; AEC Category: Q200
footprint 0603 (0603 from SM-752 data)
footprint 0603M (0603 from SM-752 data)
footprint 0603L (0603 from SM-752 data)
footprint 0603_HV (Ernesto recommended land pattern.  26 mil between pads.)
footprint 0603S
pins: 1, 2

## CMP-0085198-1
designator U?, comment TPS74601PDRVR
1-A LDO With Power-Good, DRV0006A (WSON-6); Alternate Manufacturer: Texas Instruments; SizeX_mm: 2; SizeArea_mm2: 4; AEC Category: Q200; CompType: IC; SizeAreaWB_mm2: 9; AEC Qualified: N; SizeZ_mm: 0.8
footprint DRV0006A (SON, 6-Leads, Body 2x2mm, Pitch 0.65mm, Thermal Pad 1.6x1mm, TI Recommended)
footprint DRV0006A_NV (SON, 6-Leads, Body 2x2mm, Pitch 0.65mm, Thermal Pad 1.6x1mm, TI Recommended)
pins: 1 OUT (power), 2 FB, 3 GND (power), 4 EN (in), 5 PG (out), 6 IN (power), 7 PAD (power)

## CMP-0086358-1
designator R?, comment ValueDisplayed: 0  (hidden comment: PMR03EZPJ000)
RES, 0, 0%, 0.25 W, AEC-Q200 Grade 0, 0603; Manufacturer: Rohm; Power_W: 250mW; SizeZ_mm: 1; SizeArea_mm2: 1.28; Value2: 0.25W; CompType: Resistor; SizeAreaWB_mm2: 4.68; Value_Code: 0000; Value: 0; AEC Qualified: Y; AEC Category: Q200; SizeX_mm: 1.6; SizeY_mm: 0.8
footprint 0603 (0603 from SM-752 data)
footprint 0603M (0603 from SM-752 data)
footprint 0603L (0603 from SM-752 data)
footprint 0603_HV (Ernesto recommended land pattern.  26 mil between pads.)
footprint 0603S
pins: 1, 2

## CMP-0091865-2
designator RT?, comment value 10k  (hidden comment: TMP6131DYAT)
±1% tolerance 10kΩ linear thermistor available in 0402 and 0603 package options 2-SOT-5X3 -40 to 125; Manufacturer: Texas Instruments; Max Current: 400uA; AEC Qualified: No; TJmax_C: +155°C; TaMin_C: -40°C; TempCo: 6400ppm/°C; TaMax_C: +125°C; VDC_V: 5.5V; SizeZ_mm: 0.77mm; AEC Category: Q200; CompType: IC
footprint DYA0002A-MFG
pins: 1, 2

## CMP-0091905-2
designator U?, comment TXU0304DTR
4-Bit Fixed Direction Voltage-Level Translator with SchmittTrigger Inputs, and Tri-State Outputs; Manufacturer: Texas Instruments; AEC Category: Q200; Number Of Outputs: 4; PositionCount: 1; V B Min: 1.1V; V A Max: 5.5V; CompType: IC; SizeZ_mm: 0.4mm; Standoff Height: 0mm; Logic Function Desc: Non-Inverting
footprint DTR0012A-MFG
pins: 1 VCCA (power), 2 A1 (in), 3 A2 (in), 4 A3 (in), 5 A4Y (out), 6 GND (power), 7 B4 (in), 8 B3Y (out), 9 B2Y (out), 10 B1Y (out), 11 VCCB (power), 12 OE (in)

## CMP-0092387-1
designator U?, comment TPSM82821ASILR
1-A High Efficiency Step-Down Converter MicroSiP Power Module with Integrated Inductor; Manufacturer: Texas Instruments; AEC Qualified: No; Min Supply Voltage: 2.4V; Max Supply Voltage: 5.5V; SizeZ_mm: 1.1mm; Nominal Supply Current: 4uA; TJmax_C: +125°C; Max Duty Cycle: 100%; Output Type: AdjustableProgrammable; Switching Frequency: 4MHz; Number Of Outputs: 1; Switching Topology: Buck; Output Voltage: 0.6-4V
footprint SIL0010D-MFG
pins: 1 VIN (power), 2 VIN (power), 3 EN (in), 4 PG (oc), 5 VOUT, 6 VOUT, 7 VOUT, 8 FB, 9 GND (power), 10 GND (power)

## CMP-0093649-2
designator U?, comment INA241A3IDDF
-4-V to 110-V, Bidirectional, Ultra-Precise Current Sense Amplifier With Enhanced PWM Rejection; Manufacturer: Texas Instruments; Manufacturer Part Number: INA241A3DDF; Input Offset Voltage: 0.002mV; TaMax_C: +125°C; CompType: IC; Bandwidth: 1MHz; AEC Category: Q200; Response Time: 1.5us; TaMin_C: -40°C; Nominal Supply Current: 2.5mA; Number Of Channels: 1; TJmax_C: +150°C; Standoff Height: 0mm; SizeZ_mm: 1.1mm; Min Supply Voltage: 2.7V; Input Bias Current: 40uA; Voltage Gain: 0.05V/mV; AEC Qualified: No; Max Supply Voltage: 20V
footprint DDF0008A-MFG
footprint DDF0008A-IPC_C
footprint DDF0008A-IPC_B
footprint DDF0008A-IPC_A
pins: 1 IN- (hiz), 2 GND (power), 3 REF2, 4 NC, 5 OUT, 6 Vs (power), 7 REF1, 8 IN+ (hiz)

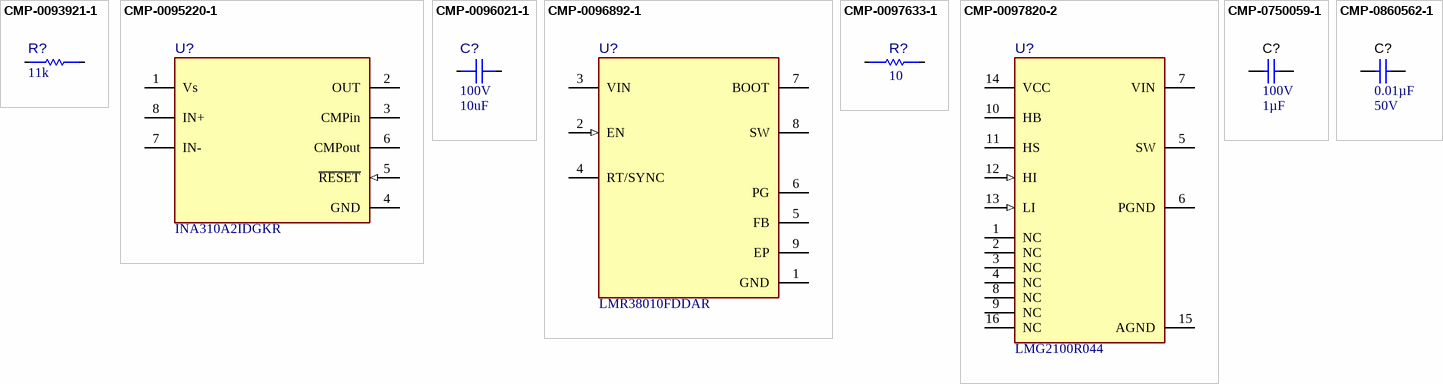
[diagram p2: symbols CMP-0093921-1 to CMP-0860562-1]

## CMP-0093921-1
designator R?, comment value 11k  (hidden comment: RMCF0402FT11K0)
11 kOhms ±1% 0.063W, 1/16W Chip Resistor 0402 (1005 Metric) Automotive AEC-Q200 Thick Film; Manufacturer: Stackpole; Manufacturer: Stackpole Electronics; VDC_V: 50V; AEC Qualified: Yes; SizeZ_mm: 0.4mm; AEC Grade: Grade 0; TempCo: 100ppm/°C; Power_W: 63mW
footprint FP-RMCF0402FT11K0_0402-MFG
footprint FP-RMCF0402FT11K0_0402-IPC_C
footprint FP-RMCF0402FT11K0_0402-IPC_B
footprint FP-RMCF0402FT11K0_0402-IPC_A
pins: 1, 2

## CMP-0095220-1
designator U?, comment INA310A2IDGKR
-4V to 110V, 1.3-MHz, Ultra-Precise Current Sense Amplifier With OpenDrain Comparator and Reference; Manufacturer: Texas Instruments; Number Of Channels: 1; Nominal Supply Current: 1.5mA; Max Supply Voltage: 20V; Bandwidth: 1300kHz; Response Time: 10us; Min Supply Voltage: 2.7V; Input Bias Current: 20uA; TaMin_C: -40°C; Standoff Height: 0.05mm; TJmax_C: +150°C; TaMax_C: +125°C; SizeZ_mm: 1.1mm; AEC Qualified: No; Voltage Gain: 0.05V/mV; Input Offset Voltage: 0.015mV
footprint DGK0008A-MFG
footprint DGK0008A-IPC_C
footprint DGK0008A-IPC_B
footprint DGK0008A-IPC_A
pins: 1 Vs (power), 2 OUT, 3 CMPin (hiz), 4 GND (power), 5 ~{RESET} (in), 6 CMPout (oc), 7 IN- (hiz), 8 IN+ (hiz)

## CMP-0096021-1
designator C?, comment VDC_V: 100V  ValueDisplayed: 10uF  (hidden comment: C3225X7R2A106K250AC)
10 µF ±10% 100V Ceramic Capacitor X7R 1210 (3225 Metric); Manufacturer: TDK; Cap_F: 10µF; AEC Qualified: No; Value: 10µF; SizeZ_mm: 2.85mm; TempCo: 15%
footprint FP-C3225X7R2A106K250AC_1210-MFG
footprint FP-C3225X7R2A106K250AC_1210-IPC_C
footprint FP-C3225X7R2A106K250AC_1210-IPC_B
footprint FP-C3225X7R2A106K250AC_1210-IPC_A
pins: 1, 2

## CMP-0096892-1
designator U?, comment LMR38010FDDAR
4.2-V to 80-V, 1-A Synchronous Buck Converter with 40-µA IQ; Manufacturer: Texas Instruments; Output Type: AdjustableProgrammable; AEC Qualified: No; Output Voltage: 1-75V; Standoff Height: 0mm; Nominal Supply Current: 40uA; Number Of Outputs: 1; TJmax_C: +150°C; Switching Frequency: 200-2200kHz; Min Supply Voltage: 4.2V; Max Duty Cycle: 97%; Max Supply Voltage: 80V; SizeZ_mm: 1.7mm
footprint DDA0008E-MFG
footprint DDA0008E-IPC_C
footprint DDA0008E-IPC_B
footprint DDA0008E-IPC_A
pins: 1 GND (power), 2 EN (in), 3 VIN (power), 4 RT/SYNC, 5 FB, 6 PG (oc), 7 BOOT, 8 SW, 9 EP

## CMP-0097633-1
designator R?, comment value 10  (hidden comment: RCC040210R0FKED)
10 Ohms ±1% 0.125W, 1/8W Chip Resistor 0402 (1005 Metric) Automotive AEC-Q200 Thick Film; Manufacturer: Vishay Dale; AEC Qualified: Yes; TempCo: 100ppm/°C; Power_W: 125mW; SizeZ_mm: 0.4mm; AEC Grade: Grade 0; VDC_V: 75V
footprint FP-RCC040210R0FKED_0402-MFG
footprint FP-RCC040210R0FKED_0402-IPC_C
footprint FP-RCC040210R0FKED_0402-IPC_B
footprint FP-RCC040210R0FKED_0402-IPC_A
pins: 1, 2

## CMP-0097820-2
designator U?, comment LMG2100R044
Manufacturer: Texas Instruments; AEC Category: Q200; CompType: IC; Standoff Height: 0mm; SizeZ_mm: 0.89mm
footprint RAR0016A-MFG
pins: 1 NC, 2 NC, 3 NC, 4 NC, 5 SW, 6 PGND (power), 7 VIN (power), 8 NC, 9 NC, 10 HB, 11 HS, 12 HI (in), 13 LI (in), 14 VCC (power), 15 AGND (power), 16 NC

## CMP-0750059-1
designator C?, comment VDC_V: 100V  ValueDisplayed: 1µF  (hidden comment: C2012X7S2A105K125AE)
CAP, CERM, 1 µF, 100 V,+/- 10%, X7S, 0805; Manufacturer: TDK; TaMax_C: 125°C; SizeAreaWB_mm2: 6.75; SizeY_mm: 1.25; Green_REACh: Incomplete; TaMin_C: -55°C; Cap_Case: 0805; CompType: Capacitor; SizeZ_mm: 1.45; U/M: EA; SizeX_mm: 2; Polarized: N; Green_Lifecycle: Active; SizeArea_mm2: 2.5; Value: 1uF; AEC Category: Q200
footprint 0805_HV (0805 with 30mil clearance between pads)
footprint 0805_HV1 (Custom footprint based on analyzing multiple manufacturer recommendations)
footprint 0805 (0805 from SM-752 data)
footprint 0805M (0805 from SM-752 data)
footprint 0805L (0805 from SM-752 data)
pins: 1, 2

## CMP-0860562-1
designator C?, comment ValueDisplayed: 0.01µF  VDC_V: 50V  (hidden comment: CL05B103KB5NNNC)
CAP, CERM, 0.01 µF, 50 V,+/- 10%, X7R, 0402; Manufacturer: Samsung Electro-Mechanics; Manufacturer: Samsung; SizeAreaWB_mm2: 3; Cap_Case: 0402; Polarized: N; TaMin_C: -55°C; SizeX_mm: 1; AEC Category: Q200; U/M: EA; SizeArea_mm2: 0.5; Cap_F: 10nF; CompType: Capacitor; Value: 0.01uF; TaMax_C: 125°C; SizeZ_mm: 0.6
footprint 0402 (0402 from SM-752 data)
footprint 0402M (0402 from SM-752 data)
footprint 0402L (0402 from SM-752 data)
footprint 0402S (Based on C0402S footprint from PADS legacy)
pins: 1, 2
